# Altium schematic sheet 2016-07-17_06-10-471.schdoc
size 261 x 111 mm; SheetNumber: 1; SheetTotal: 1
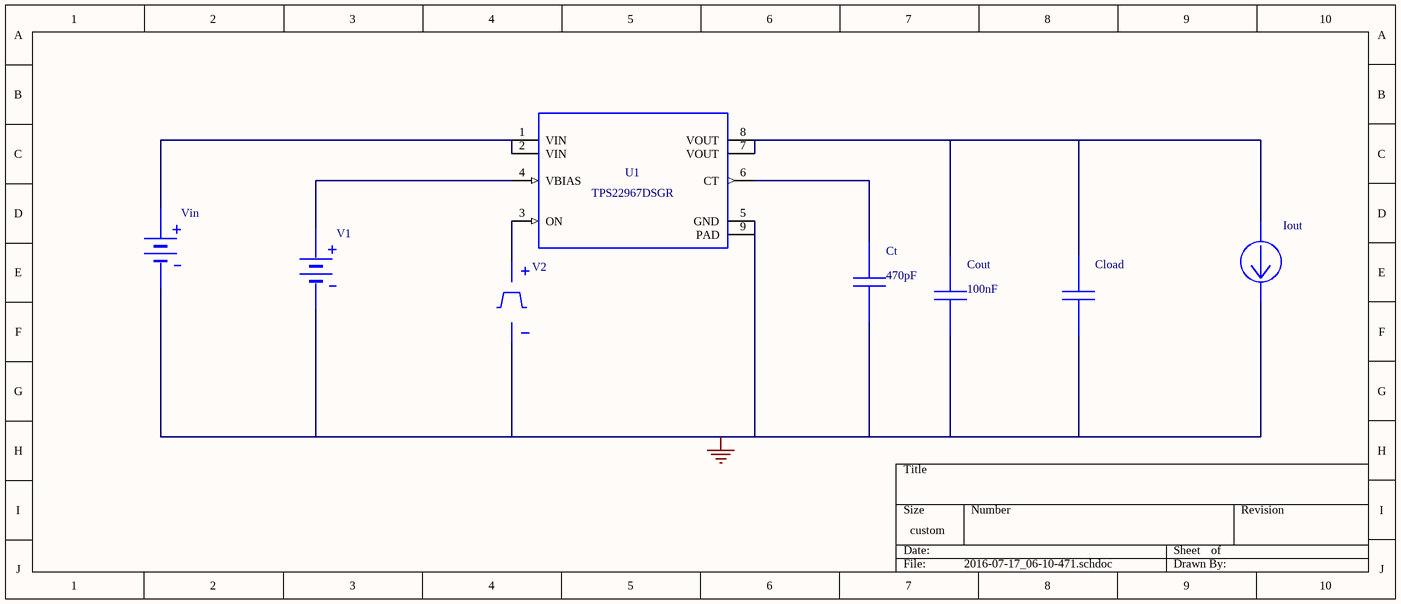
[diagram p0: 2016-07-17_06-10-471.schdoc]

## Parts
Cload  GRM21BR71E104KA01L  (value not drawn)
Cout  value 100nF  (hidden comment: GRM155R60J104KA01D)
Ct  value 470pF  (hidden comment: CC0805KRX7R9BB471)
Iout  WB_CURRENT_LOAD  (value not drawn)
U1  TPS22967DSGR
V1  WB_PRIMITIVE_BATTERY  (value not drawn)
V2  WB_PRIM_PWL_VOLTAGE_SOURCE  (value not drawn)
Vin  WB_BATTERY  (value not drawn)

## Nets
0: Cload.2 Cout.2 Ct.2 Iout.2(-) U1.5(GND) U1.9(PAD) V1.2(-) V2.2(-) Vin.2(-)
NetCload_1: Cload.1 Cout.1 Iout.1(+) U1.7(VOUT) U1.8(VOUT)
NetCt_1: Ct.1 U1.6(CT)
NetU1_1: U1.1(VIN) U1.2(VIN) Vin.1(+)
NetU1_3: U1.3(ON) V2.1(+)
NetU1_4: U1.4(VBIAS) V1.1(+)

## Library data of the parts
Cload = GRM21BR71E104KA01L: WB_PRIMITIVE_CAP; Manufacturer Name: WB_PRIMITIVE_CAPACITOR
Cout = GRM155R60J104KA01D: GRM155R60J104KA0; Manufacturer Name: MuRata
Ct = CC0805KRX7R9BB471: CC0805KRX7R9BB47; Manufacturer Name: Yageo America
U1 = TPS22967DSGR: Manufacturer Name: Texas Instruments
V1 = WB_PRIMITIVE_BATTERY: WB_PRIMITIVE_BAT
V2 = WB_PRIM_PWL_VOLTAGE_SOURCE: WB_PRIM_PWL_VOLT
